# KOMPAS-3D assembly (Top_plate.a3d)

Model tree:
1. X Axis
2. Y Axis
3. Z Axis
4. Origin
5. Linear Pattern:1  (labels: Instance ( 2, 1 );; Instance ( 3, 1 );; Instance ( 4, 1 );; Instance ( 5, 1 );)
     Included Angle = 90; N 2 = 1; Spacing 2 = 10; Orientation = 1

Expressions: TP_W+(2*Delta); TP_W+(2*Delta)-100
Referenced files in D:\Documents and Settings\kashirsky\Рабочий стол\My sample\: skrzynia1.a3d|NT, skrzynia1.a3d|L, skrzynia1.a3d|W, skrzynia1.a3d|Delta, Top_plate.m3d, rail4.m3d, Top_plate.a3d, Top_plate.spw, Box.cdw, skrzynia1.a3d, skrzynia1.spw
Referenced files in C:\Work\01 К О М П А С\Модели примеры\2009_04_For_Poland_AXAPACK\My sample\: skrzynia1.a3d
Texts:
  Plate 04
  Wood (15% moisture content)
  Three Point Plane
  Plane at Angle
  Line and Point Plane
  Axis through Two Vertices
  Axis of Feature
  Axis of Conical Surface
  Axis through Edge
  Trim by Surface
  Trim by Sketch
  Intersection Axis of Two Planes
  Two Line Plane
  Line and Face Plane
  Pattern by Sample
  Point in CM
  Feature with No History
  Linear Dimension from Line to Point
  Surface Finish Symbol
  Geometric Tolerance Symbol
  Leader #1
  Leader #2
  Leader #3
  Shape Deviations and Datum
  Node point number
  Mark of coordination axis
  Node point designation
  Mark/Reference designation with leader
  Mark/reference designation on line
  Mark/Reference designation without leader
  LR4
  Rail 04
  Instance ( 2, 1 );
  Instance ( 3, 1 );
  Instance ( 4, 1 );
  Instance ( 5, 1 );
